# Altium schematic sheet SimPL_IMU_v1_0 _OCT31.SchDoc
size 302 x 236 mm
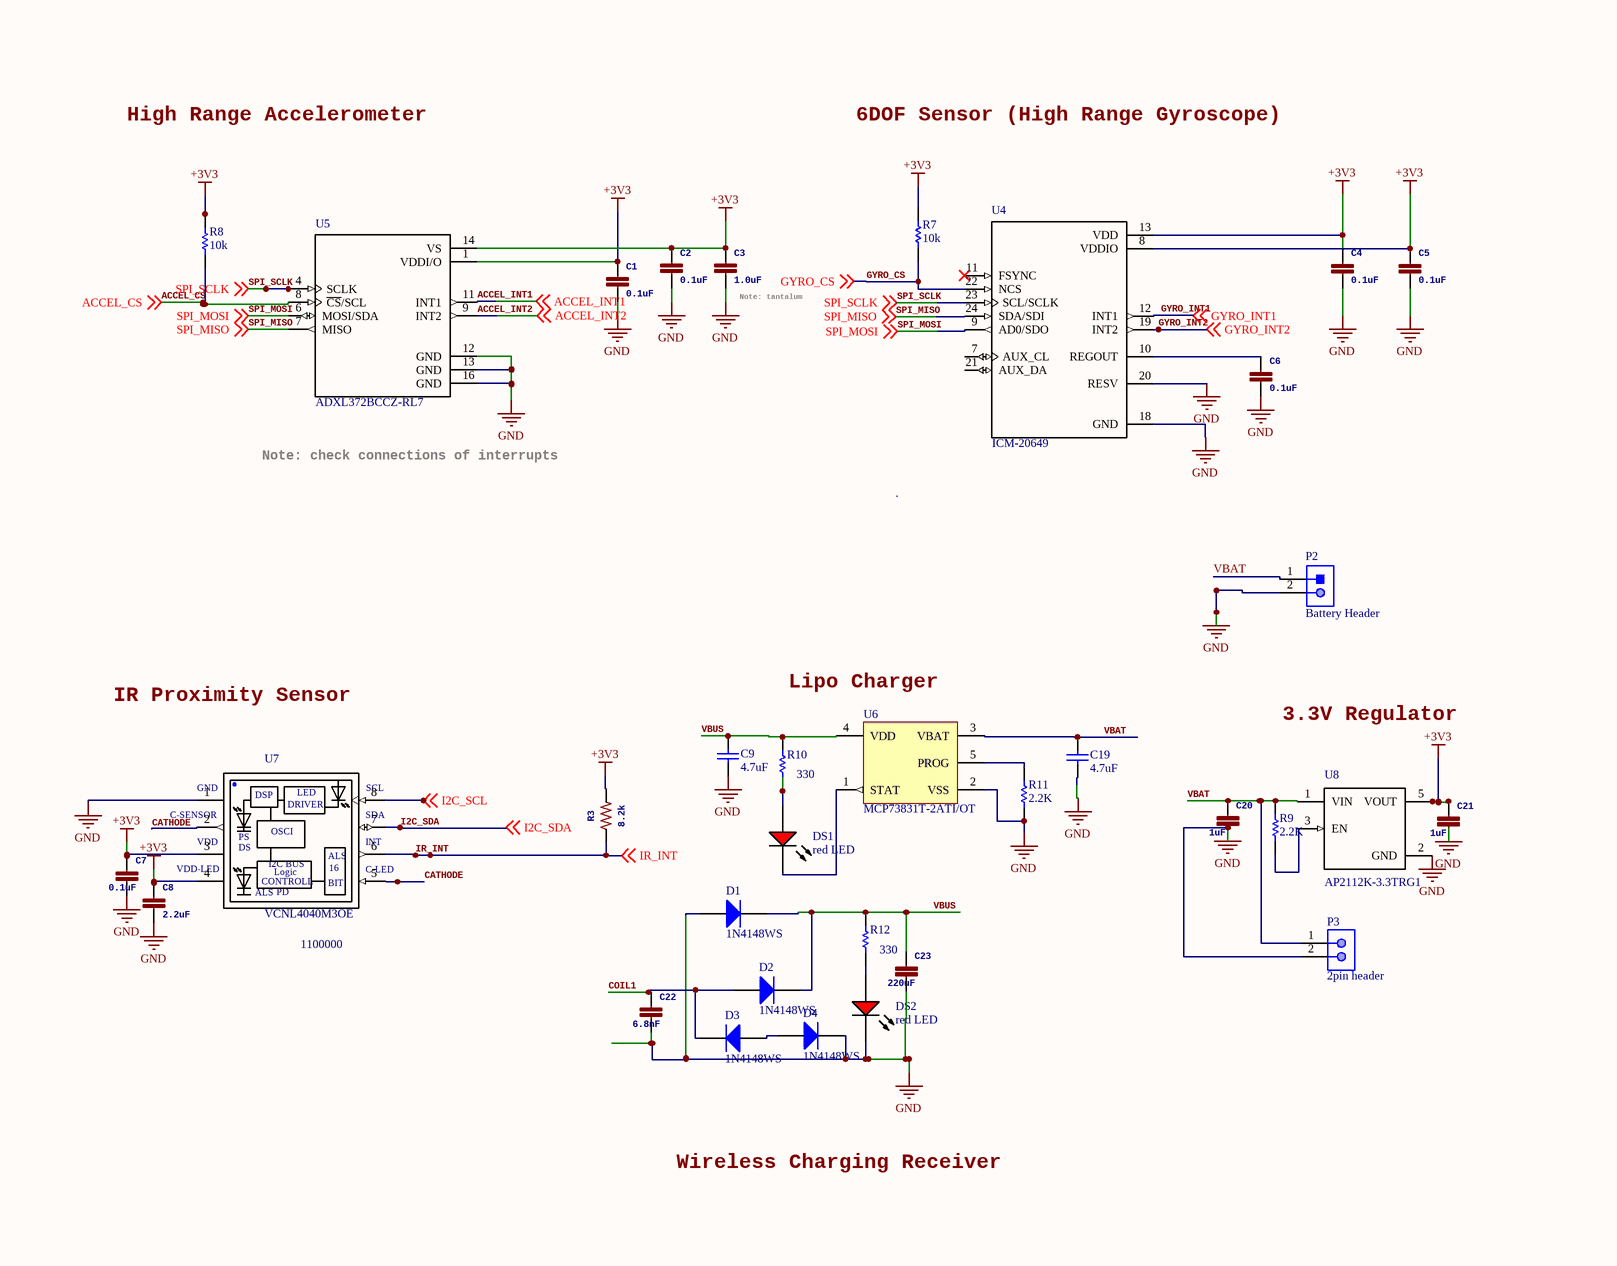
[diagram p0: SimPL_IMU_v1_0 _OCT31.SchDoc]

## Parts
C1  0.1uF  [0402]
C2  0.1uF  [0402]
C3  1.0uF  [0402]
C4  0.1uF  [0402]
C5  0.1uF  [0402]
C6  0.1uF  [0402]
C7  0.1uF  [0402]
C8  2.2uF  [0402]
C9  4.7uF  [CAPC1005X65X10ML15]
C19  4.7uF  [CAPC1005X65X10ML15]
C20  1uF  [0402]
C21  1uF  [0402]
C22  6.8nF  [0402]
C23  220uF  [0402]
D1  1N4148WS  [DIOD-SOD323-2-A_V]
D2  1N4148WS  [DIOD-SOD323-2-A_V]
D3  1N4148WS  [DIOD-SOD323-2-A_V]
D4  1N4148WS  [DIOD-SOD323-2-A_V]
DS1  red LED  [VISH-TLMS1000_V]
DS2  red LED  [VISH-TLMS1000_V]
P2  Battery Header  [JST-S2B-PH-K-S_V]
P3  2pin header  [AMPH-68000-102HLF_V]
R3  8.2k  [0603]
R7  10k  [RESC1005X40X25NL05T05]
R8  10k  [RESC1005X40X25NL05T05]
R9  2.2K  [RESC1005X40X25ML10T10]
R10  330  [RESC2013X50X30NL20T20]
R11  2.2K  [RESC1005X40X25ML10T10]
R12  330  [RESC2013X50X30NL20T20]
U4  ICM-20649  [*QFN40P300X300X95-24N]
U5  ADXL372BCCZ-RL7  [*PQFN50P322X300X114-16N]
U6  MCP73831T-2ATI/OT  [SOT-23-OT5_M]
U7  VCNL4040M3OE  [*VISHAY_VCNL4040_4X2X1.1]
U8  AP2112K-3.3TRG1  [*SOT95P285X140-5N]

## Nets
+3V3: C1.1 C2.1 C3.1 C4.1 C5.1 C7.1 C8.1 C21.1 R3.2 R7.2 R8.2 U4.8(VDDIO) U4.13(VDD) U5.1(VDDI/O) U5.14(VS) U7.3(VDD) U7.4(VDD-LED) U8.5(VOUT)
GND: C1.2 C2.2 C3.2 C4.2 C5.2 C6.2 C7.2 C8.2 C9.1 C19.1 C20.2 C21.2 C22.2 C23.2 D1.1(A) D4.2(K) DS2.2(K) P2.2 P3.2 R11.1 U4.18(GND) U4.20(RESV) U5.12(GND) U5.13(GND) U5.16(GND) U6.2(VSS) U7.1(GND) U8.2(GND)
ACCEL_CS: R8.1 U5.8(~{CS}/SCL) ; off-sheet ACCEL_CS
ACCEL_INT1: U5.11(INT1) ; off-sheet ACCEL_INT1
ACCEL_INT2: U5.9(INT2) ; off-sheet ACCEL_INT2
CATHODE: U7.2(C-SENSOR) U7.5(C-LED)
COIL1: C22.1 D2.1(A) D3.2(K)
GYRO_CS: R7.1 U4.22(NCS) ; off-sheet GYRO_CS
GYRO_INT1: U4.12(INT1) ; off-sheet GYRO_INT1
GYRO_INT2: U4.19(INT2) ; off-sheet GYRO_INT2
I2C_SCL: U7.8(SCL) ; off-sheet I2C_SCL
I2C_SDA: U7.7(SDA) ; off-sheet I2C_SDA
IR_INT: R3.1 U7.6(INT) ; off-sheet IR_INT
SPI_MISO: U4.24(SDA/SDI) U5.7(MISO) ; off-sheet SPI_MISO
SPI_MOSI: U4.9(AD0/SDO) U5.6(MOSI/SDA) ; off-sheet SPI_MOSI
SPI_SCLK: U4.23(SCL/SCLK) U5.4(SCLK) ; off-sheet SPI_SCLK
VBAT: C19.2 C20.1 P2.1 P3.1 R9.2 U6.3(VBAT) U8.1(VIN)
VBUS: C9.2 C23.1 D1.2(K) D2.2(K) R10.2 R12.2 U6.4(VDD)
NetC6_1: C6.1 U4.10(REGOUT)
NetD3_1: D3.1(A) D4.1(A)
NetDS1_1: DS1.1(A) R10.1
NetDS1_2: DS1.2(K) U6.1(STAT)
NetDS2_1: DS2.1(A) R12.1
NetR9_1: R9.1 U8.3(EN)
NetR11_2: R11.2 U6.5(PROG)

Not connected (* = marked no-connect by the designer): U4 7(AUX_CL) 11(FSYNC)* 21(AUX_DA)

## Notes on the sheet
- High Range Accelerometer
- 6DOF Sensor (High Range Gyroscope)
- (near C3) Note: tantalum
- Note: check connections of interrupts
- IR Proximity Sensor
- Lipo Charger
- 3.3V Regulator
- 1100000
- Wireless Charging Receiver
- Labels drawn without touching a wire or pin: I2C_SDA

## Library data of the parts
C1 C2 C4-C7 = 0.1UF-0402-16V-10%: 0.1ÂµF ceramic capacitors    A capacitor is a passive two-terminal electrical component used to store electrical energy temporarily in an electric field.; GateName_1: G$1; SymbolName_1: CAP; PROD_ID: CAP-12416
C3 = 1.0UF-0402-16V-10%: 1ÂµF ceramic capacitors    A capacitor is a passive two-terminal electrical component used to store electrical energy temporarily in an electric field.; GateName_1: G$1; SymbolName_1: CAP; PROD_ID: CAP-12417
C8 C20-C23 = 0.1UF-0402-16V-10%: 0.1ÂµF ceramic capacitors    A capacitor is a passive two-terminal electrical component used to store electrical energy temporarily in an electric field.; GateName_1: G$1; SymbolName_1: CAP; DeviceSetName: 0.1UF; PROD_ID: CAP-12416
C9 C19 = CMP-2000-05438-1: Chip Capacitor, 4.7 uF, +/- 20%, 10 V, -55 to 85 degC, 0402 (1005 Metric), RoHS, Tape and Reel; PCN Part Number: MLCCPartNumberChange30/Nov/2012; Manufacturer: TDK; Other Names: 445-8023-1; Voltage - Rated: 10V; Temperature Coefficient: X5R; Online Catalog: CSeries,GeneralPurpose; Capacitance: 4.7µF; Kits: 445-9021-KIT-ND-KITMLCC100PF-10UF04026.3-50V445-9003-KIT-ND-KITCAPCERHICAPMLCCSMD; Product Training Modules: CSeriesGeneralApplicationsSEAT,CCV,andTVCLDesignToolsGuidetoReplacinganElectrolyticCapacitorwithanMLCC
D1-D4 = CMP-1667-00004-1: Fast Switching Diode, 75 V, 0.3 A, -65 to 150 degC, 2-Pin SOD323, RoHS, Tape and Reel
DS1 DS2 = CMP-2000-07254-1: Low Current LED, 40 mW, 1.8 V, -40 to 100 degC, 2-Pin SMD (0603), RoHS, Tape and Reel; Manufacturer: Vishay; Lens Shape: Rectangular; Automotive Qualification Standard: AEC-Q100; Wavelength Typ: 636nm; SVHC: ToBeAdvised; Bulb Size: 1.6mmx0.8mm; Forward Voltage: 1.8V; Luminous Intensity: 4mcd; Forward Current If: 2mA; Viewing Angle: 80°
P2 = CMP-1755-00004-1: Male Header, Pitch 2 mm, 1 x 2 Position, Height 4.8 mm, Tail Length 3.4 mm, -25 to 85 degC, RoHS, Bulk; Case\Package: Radial; Tolerance: 20%; Capacitance: 10 uF; Voltage Rating (DC): 50 V
P3 = CMP-2000-05666-1: Male Header, Pitch 2.54 mm, 1 x 2 Position, Height 8.38 mm, Tail Length 2.41 mm, RoHS, Bulk; Number of Positions: 2; Insulation Resistance: 5000MOhms; Voltage Rating: 1.5kV; Mounting Angle: Vertical; Pitch: 2.54mm; Brand: FCI; Current Rating: 3A; Mating Post Length: 5.84mm
R3 = 8.2KOHM-0603-1/10W-5%: 8.2kÎ© resistor    A resistor is a passive two-terminal electrical component that implements electrical resistance as a circuit element. Resistors act to reduce current flow, and, at the same time, act to lower voltage levels within circuits. - Wikipedia; GateName_1: G$1; PROD_ID: RES-10646
R7 R8 = CMP-2002-00607-3: Chip Resistor, 10 KOhm, +/- 1%, 100 mW, -55 to 155 degC, 0402 (1005 Metric), RoHS, Tape and Reel; Manufacturer: Basic Passives; PartNumber: ERJ-2RKF1002X; Case\/Package: 0402; Resistance: 10 KOhm; Voltage Rating: 50 V; Power Rating: 100 mW
R9 R11 = CMP-2002-06097-1: Part Number: MC00625W040212K2; Manufacturer: Multicomp
R10 R12 = CMP-2001-03823-1: Manufacturer: Vishay Dale; Part Number: CRCW0805330RFKEA
U4 = ICM-20649: Wide-Range 6-Axis MEMS MotionTracking Device for Sports and High Impact Applications; MF: TDK InvenSense
U5 = ADXL372BCCZ-RL7: / Accelerometer Triple Â±200g 2.5V 16-Pin LGA T/R /; MF: Analog Devices
U6 = CMP-0133-00144-1: Miniature Single-Cell, Fully Integrated Li-Ion, Li-Polymer Charge Management Controller, 4.2V, 5-Pin SOT-23, Industrial Temperature, Tape and Reel
U7 = VCNL4040M3OE: VCNL4040 Series 3.6 V 200 mm 16 Bit I2C SMT Proximity and Ambient Light Sensor; MF: Vishay
U8 = AP2112K-3.3TRG1: AP2112 Series 0.6 A 3.3 V Fixed Output SMT LDO Linear Regulator - SOT23-5; MF: Diodes Inc.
